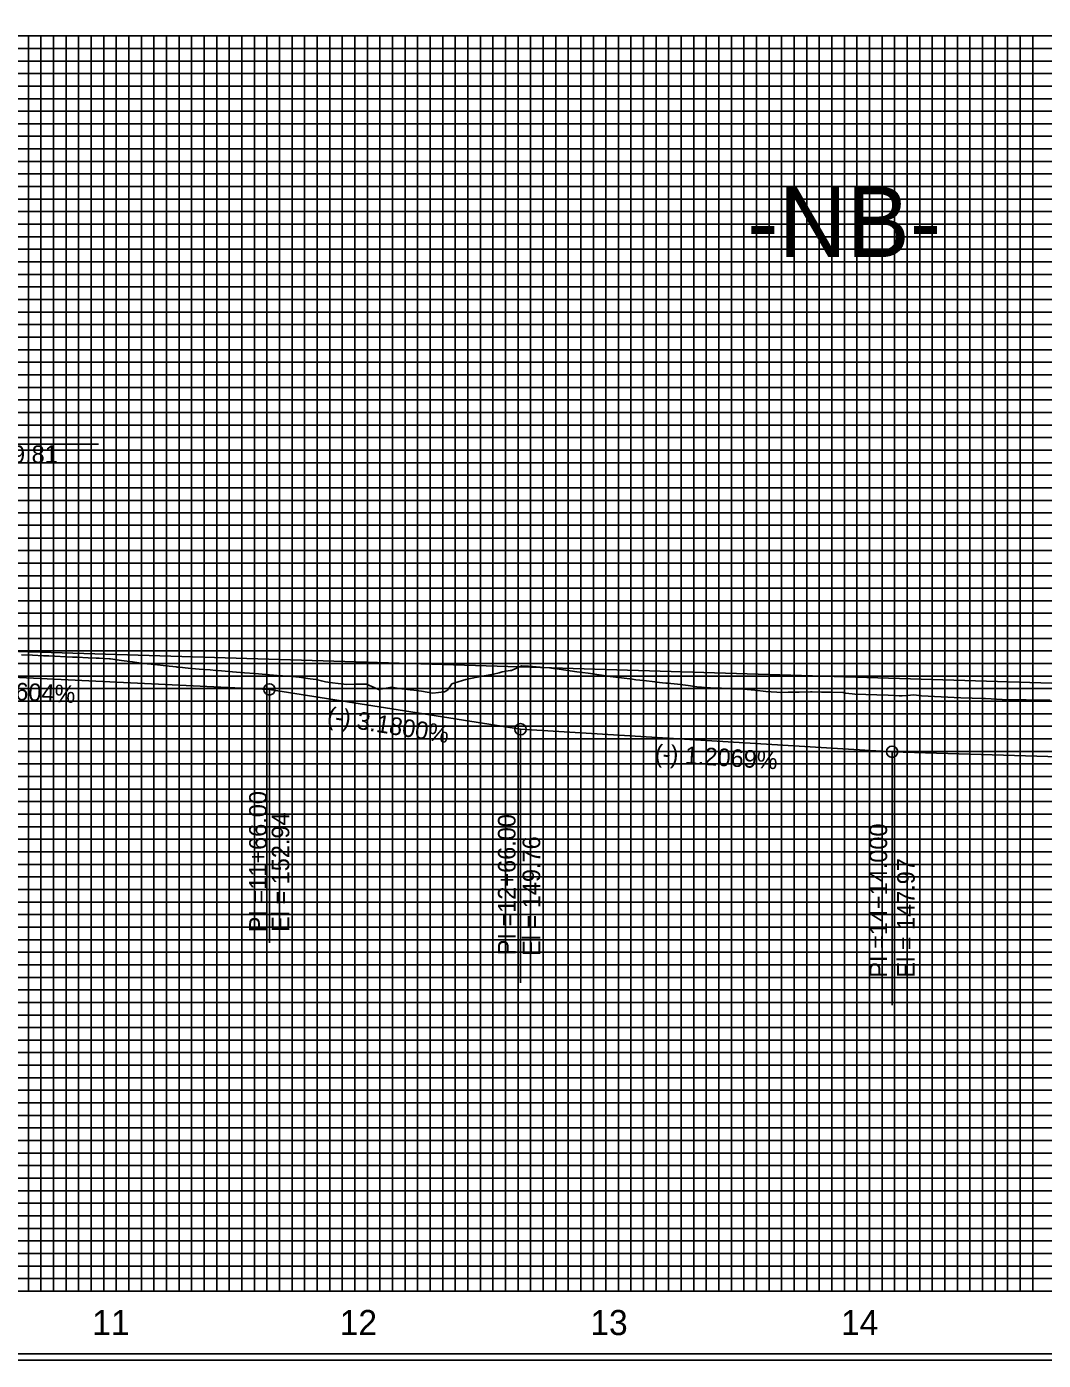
# Model space of a CAD drawing. Extents: x 573468 to 580768, y -57414 to -51768.
# Drawn here: x 579215 to 579619, y -55191 to -54660 of the extents above; entities that cross this region are included whole.
import ezdxf

# ---------------------------------------------------------------- set-up
doc = ezdxf.new("R2010")
doc.units = 0
for name, color, linetype in [('Exist Vertical Profile Ground Line', 7, 'Continuous'), ('Exist Vertical Profile Horizontal Axis Label Major', 7, 'Continuous'), ('Prop Grid Mask', 7, 'Continuous'), ('Prop PFL Text', 7, 'Continuous'), ('Prop Vertical Profile Ditch Grade Right', 7, 'Continuous'), ('Prop Vertical Profile Ditch Grade Right Label', 7, 'Continuous'), ('Prop Vertical Profile Grade', 7, 'Continuous'), ('Prop VPI Ditch Grade Right Label', 7, 'Continuous'), ('Sheet DOT Grid CELL', 7, 'Continuous'), ('Sheet Layout Profile Border Port 2', 7, 'Continuous'), ('Sheet Plot Border Inside CELL', 7, 'Continuous'), ('Sheet Profile CELL', 7, 'Continuous'), ('Sheet Profile Grid Major CELL', 7, 'Continuous'), ('Sheet Profile Grid Middle CELL', 7, 'Continuous'), ('Sheet Profile Grid Minor CELL', 7, 'Continuous')]:
    doc.layers.add(name, color=color, linetype=linetype)

msp = doc.modelspace()

# ---------------------------------------------------------------- linework, layer by layer
at = {"layer": 'Exist Vertical Profile Ground Line'}
for points in [[(579212.43, -54910.09), (579216.86, -54910.27), (579221.28, -54910.45), (579223.28, -54910.54), (579225.71, -54910.65), (579230.13, -54910.87), (579232.72, -54911), (579234.56, -54911.07), (579238.99, -54911.25), (579242.22, -54911.37), (579243.41, -54911.43), (579247.48, -54911.64), (579247.84, -54911.69), (579252.26, -54912.31), (579256.69, -54912.91), (579260.14, -54913.38), (579261.11, -54913.49), (579265.54, -54913.97), (579269.96, -54914.45), (579274.07, -54914.89), (579274.39, -54914.93), (579275.36, -54915.04), (579278.81, -54915.35), (579283.24, -54915.74), (579287.66, -54916.12), (579289.84, -54916.31), (579292.09, -54916.5), (579296.52, -54916.87), (579298.15, -54917.01), (579301.24, -54917.24), (579305.37, -54917.56), (579309.79, -54917.91), (579314.22, -54918.25), (579318.64, -54918.59), (579321.75, -54918.82), (579323.07, -54919.01), (579327.49, -54919.63), (579329.77, -54919.95), (579331.92, -54920.44), (579333.59, -54920.81), (579336.34, -54921.17), (579340.77, -54921.74), (579341.75, -54921.87), (579345.2, -54921.8), (579349.62, -54921.72), (579349.92, -54921.71), (579354.05, -54923.63), (579354.7, -54923.94), (579358.47, -54923.26), (579359.84, -54923.01), (579362.9, -54923.45), (579366.21, -54923.91), (579367.32, -54924), (579368.73, -54924.15), (579371.75, -54924.6), (579376.3, -54925.39), (579378.56, -54925.08), (579380.6, -54924.85), (579380.94, -54924.81), (579382.1, -54924.13), (579383.86, -54921.59), (579385.02, -54921.25), (579389.45, -54919.97), (579393.87, -54919.04), (579397.59, -54918.25), (579398.3, -54918.14), (579400.46, -54917.8), (579402.73, -54917.22), (579403.94, -54916.9), (579405.52, -54916.62), (579407.15, -54916.34), (579407.59, -54916.27), (579411.58, -54914.44), (579414.4, -54914.55), (579416, -54914.69), (579420.43, -54915.1), (579422.81, -54915.32), (579424.41, -54915.48), (579424.85, -54915.54), (579429.28, -54916.18), (579433.7, -54916.81), (579438.13, -54917.44), (579442.55, -54918.07), (579446.98, -54918.69), (579448.07, -54918.85), (579451.41, -54919.26), (579455.83, -54919.82), (579457.12, -54919.98), (579460.26, -54920.34), (579464.68, -54920.85), (579466.56, -54921.07), (579467.82, -54921.2), (579469.11, -54921.33), (579469.79, -54921.4), (579473.7, -54921.71), (579477.96, -54922.29), (579482.38, -54922.9), (579483.28, -54923.02), (579484.16, -54923.13), (579484.53, -54923.15), (579486.81, -54923.24)], [(579486.81, -54923.24), (579491.23, -54923.4), (579495.66, -54923.56), (579500.08, -54923.73), (579504.51, -54924.19), (579508.94, -54924.64), (579511.05, -54924.85), (579513.36, -54925), (579514.73, -54925.09), (579517.79, -54925.02), (579522.21, -54924.91), (579526.64, -54924.8), (579527.43, -54924.78), (579531.06, -54924.92), (579533.39, -54925.01), (579535.49, -54925.02), (579539.6, -54925.04), (579539.91, -54925.14), (579540.58, -54925.34), (579543.32, -54925.68), (579544.34, -54925.72), (579548.76, -54925.88), (579553.19, -54926.04), (579557.62, -54926.2), (579562.04, -54926.36), (579563.25, -54926.4), (579566.47, -54926.15), (579567.86, -54926.03), (579570.89, -54926.4), (579586.52, -54927.23), (579595.63, -54927.48), (579596.44, -54927.51), (579603.07, -54927.83), (579622.15, -54928.11)]]:
    msp.add_lwpolyline(points, dxfattribs=at)
at = {"layer": 'Prop Grid Mask'}
msp.add_lwpolyline([(579495.21, -54713.55), (579595.21, -54713.55), (579595.21, -54763.55), (579495.21, -54763.55)], close=True, dxfattribs=at)
at = {"layer": 'Prop PFL Text'}
msp.add_line((579145.02, -54826.15), (579243.08, -54826.15), dxfattribs=at)
at = {"layer": 'Prop Vertical Profile Ditch Grade Right'}
msp.add_lwpolyline([(579109.21, -54914.15), (579311.21, -54923.85), (579411.21, -54939.75), (579559.21, -54948.68), (579909.21, -54959.25), (580001.21, -54968.2)], dxfattribs=at)
at = {"layer": 'Prop Vertical Profile Ditch Grade Right Label'}
for p, q in [((579311.21, -54923.85), (579311.21, -55024.81)), ((579411.21, -54939.75), (579411.21, -55040.71)), ((579559.21, -54948.68), (579559.21, -55049.64))]:
    msp.add_line(p, q, dxfattribs=at)
for centre in [(579311.21, -54923.85), (579411.21, -54939.75), (579559.21, -54948.68)]:
    msp.add_circle(centre, 2.25, dxfattribs=at)
at = {"layer": 'Prop Vertical Profile Grade'}
msp.add_line((579145.02, -54906.75), (579945.21, -54931.16), dxfattribs=at)
at = {"layer": 'Sheet DOT Grid CELL'}
for p, q in [((578845.21, -54663.55), (580345.1, -54663.55)), ((579245.21, -54663.55), (579245.21, -55163.55)), ((579295.21, -54663.55), (579295.21, -55163.55)), ((579345.21, -54663.55), (579345.21, -55163.55)), ((579395.21, -54663.55), (579395.21, -55163.55)), ((579445.21, -54663.55), (579445.21, -55163.55)), ((579495.21, -54663.55), (579495.21, -55163.55)), ((579545.21, -54663.55), (579545.21, -55163.55)), ((579595.21, -54663.55), (579595.21, -55163.55)), ((578845.21, -54713.55), (580345.1, -54713.55)), ((578845.21, -54763.55), (580345.1, -54763.55)), ((578845.21, -54813.55), (580345.1, -54813.55)), ((578845.21, -54863.55), (580345.1, -54863.55)), ((578845.21, -54913.55), (580345.1, -54913.55)), ((578845.21, -54963.55), (580345.1, -54963.55)), ((578845.21, -55013.55), (580345.1, -55013.55)), ((578845.21, -55063.55), (580345.1, -55063.55)), ((578845.21, -55113.55), (580345.1, -55113.55))]:
    msp.add_line(p, q, dxfattribs=at)
at = {"layer": 'Sheet Layout Profile Border Port 2'}
msp.add_lwpolyline([(578895.21, -54663.55), (580295.21, -54663.55), (580295.21, -55163.55), (578895.21, -55163.55)], close=True, dxfattribs=at)
at = {"layer": 'Sheet Plot Border Inside CELL'}
msp.add_lwpolyline([(578691.21, -55191.1), (580357.71, -55191.1), (580357.71, -54136), (578691.21, -54136)], close=True, dxfattribs=at)
at = {"layer": 'Sheet Profile CELL'}
for p, q in [((578845.21, -54663.55), (580345.21, -54663.55)), ((580345.21, -55163.55), (578845.21, -55163.55)), ((578845.21, -55188.55), (580345.21, -55188.55))]:
    msp.add_line(p, q, dxfattribs=at)
msp.add_lwpolyline([(580345.21, -54138.55), (578845.21, -54138.55), (578845.21, -55188.55), (580345.21, -55188.55)], close=True, dxfattribs=at)
at = {"layer": 'Sheet Profile Grid Major CELL'}
for p, q in [((579345.21, -54663.55), (579395.21, -54663.55)), ((579445.21, -54663.55), (579495.21, -54663.55)), ((579545.21, -54663.55), (579595.21, -54663.55))]:
    msp.add_line(p, q, dxfattribs=at)
for points in [[(579195.21, -55163.55), (579245.21, -55163.55), (579245.21, -54663.55), (579295.21, -54663.55), (579295.21, -55163.55), (579345.21, -55163.55), (579345.21, -54663.55), (579395.21, -54663.55), (579395.21, -55163.55), (579445.21, -55163.55), (579445.21, -54663.55), (579495.21, -54663.55), (579495.21, -55163.55), (579545.21, -55163.55), (579545.21, -54663.55), (579595.21, -54663.55), (579595.21, -55163.55), (579645.21, -55163.55)], [(580345.21, -54713.55), (578845.21, -54713.55)], [(580345.21, -54763.55), (578845.21, -54763.55), (578845.21, -54813.55), (580345.21, -54813.55)], [(580345.21, -54863.55), (578845.21, -54863.55), (578845.21, -54913.55), (580345.21, -54913.55)], [(580345.21, -54963.55), (578845.21, -54963.55), (578845.21, -55013.55), (580345.21, -55013.55)], [(580345.21, -55063.55), (578845.21, -55063.55), (578845.21, -55063.55), (578845.21, -55113.55), (580345.21, -55113.55)], [(580345.21, -55163.55), (578845.21, -55163.55)]]:
    msp.add_lwpolyline(points, dxfattribs=at)
at = {"layer": 'Sheet Profile Grid Middle CELL'}
for points in [[(579170.21, -54663.55), (579220.21, -54663.55), (579220.21, -55163.55), (579270.21, -55163.55), (579270.21, -54663.55), (579320.21, -54663.55), (579320.21, -55163.55), (579370.21, -55163.55), (579370.21, -54663.55), (579420.21, -54663.55), (579420.21, -55163.55), (579470.21, -55163.55), (579470.21, -55163.55), (579470.21, -54663.55), (579520.21, -54663.55), (579520.21, -55163.55), (579570.21, -55163.55), (579570.21, -54663.55), (579620.21, -54663.55)], [(578845.21, -54688.55), (580345.21, -54688.55)], [(580345.21, -54738.55), (578845.21, -54738.55), (578845.21, -54788.55), (580345.21, -54788.55)], [(580345.21, -54838.55), (578845.21, -54838.55), (578845.21, -54888.55), (580345.21, -54888.55)], [(580345.21, -54938.55), (578845.21, -54938.55), (578845.21, -54988.55), (580345.21, -54988.55)], [(580345.21, -55038.55), (578845.21, -55038.55), (578845.21, -55088.55), (580345.21, -55088.55)], [(580345.21, -55138.55), (578845.21, -55138.55)]]:
    msp.add_lwpolyline(points, dxfattribs=at)
at = {"layer": 'Sheet Profile Grid Minor CELL'}
for p, q in [((578895.21, -54668.55), (580295.21, -54668.55)), ((580295.21, -54673.55), (578895.21, -54673.55)), ((578895.21, -54678.55), (580295.21, -54678.55)), ((580295.21, -54683.55), (578895.21, -54683.55)), ((578895.21, -54693.55), (580295.21, -54693.55)), ((580295.21, -54698.55), (578895.21, -54698.55)), ((578895.21, -54703.55), (580295.21, -54703.55)), ((580295.21, -54708.55), (578895.21, -54708.55)), ((578895.21, -54718.55), (580295.21, -54718.55)), ((580295.21, -54723.55), (578895.21, -54723.55)), ((578895.21, -54728.55), (580295.21, -54728.55)), ((580295.21, -54733.55), (578895.21, -54733.55)), ((578895.21, -54743.55), (580295.21, -54743.55)), ((580295.21, -54748.55), (578895.21, -54748.55)), ((578895.21, -54753.55), (580295.21, -54753.55)), ((580295.21, -54758.55), (578895.21, -54758.55)), ((578895.21, -54768.55), (580295.21, -54768.55)), ((580295.21, -54773.55), (578895.21, -54773.55)), ((578895.21, -54778.55), (580295.21, -54778.55)), ((580295.21, -54783.55), (578895.21, -54783.55)), ((578895.21, -54793.55), (580295.21, -54793.55)), ((580295.21, -54798.55), (578895.21, -54798.55)), ((578895.21, -54803.55), (580295.21, -54803.55)), ((580295.21, -54808.55), (578895.21, -54808.55)), ((578895.21, -54818.55), (580295.21, -54818.55)), ((580295.21, -54823.55), (578895.21, -54823.55)), ((578895.21, -54828.55), (580295.21, -54828.55)), ((580295.21, -54833.55), (578895.21, -54833.55)), ((578895.21, -54843.55), (580295.21, -54843.55)), ((580295.21, -54848.55), (578895.21, -54848.55)), ((578895.21, -54853.55), (580295.21, -54853.55)), ((580295.21, -54858.55), (578895.21, -54858.4)), ((578895.21, -54868.55), (580295.21, -54868.55)), ((580295.21, -54873.55), (578895.21, -54873.55)), ((578895.21, -54878.55), (580295.21, -54878.55)), ((580295.21, -54883.55), (578895.21, -54883.55)), ((578895.21, -54893.55), (580295.21, -54893.55)), ((580295.21, -54898.55), (578895.21, -54898.55)), ((578895.21, -54903.55), (580295.21, -54903.55)), ((580295.21, -54908.55), (578895.21, -54908.55)), ((578895.21, -54918.55), (580295.21, -54918.55)), ((580295.21, -54923.55), (578895.21, -54923.55)), ((578895.21, -54928.55), (580295.21, -54928.55)), ((580295.21, -54933.55), (578895.21, -54933.55)), ((578895.21, -54943.55), (580295.21, -54943.55)), ((580295.21, -54948.55), (578895.21, -54948.55)), ((578895.21, -54953.55), (580295.21, -54953.55)), ((580295.21, -54958.55), (578895.21, -54958.55)), ((578895.21, -54968.55), (580295.21, -54968.55)), ((580295.21, -54973.55), (578895.21, -54973.55)), ((578895.21, -54978.55), (580295.21, -54978.55)), ((580295.21, -54983.55), (578895.21, -54983.55)), ((578895.21, -54993.55), (580295.21, -54993.55)), ((580295.21, -54998.55), (578895.21, -54998.55)), ((578895.21, -55003.55), (580295.21, -55003.55)), ((580295.21, -55008.55), (578895.21, -55008.55)), ((578895.21, -55018.55), (580295.21, -55018.55)), ((580295.21, -55023.55), (578895.21, -55023.55)), ((578895.21, -55028.55), (580295.21, -55028.55)), ((580295.21, -55033.55), (578895.21, -55033.55)), ((578895.21, -55043.55), (580295.21, -55043.55)), ((580295.21, -55048.55), (578895.21, -55048.55)), ((578895.21, -55053.55), (580295.21, -55053.55)), ((580295.21, -55058.55), (578895.21, -55058.55)), ((578895.21, -55068.55), (580295.21, -55068.55)), ((580295.21, -55073.55), (578895.21, -55073.55)), ((578895.21, -55078.55), (580295.21, -55078.55)), ((580295.21, -55083.55), (578895.21, -55083.55)), ((578895.21, -55093.55), (580295.21, -55093.55)), ((580295.21, -55098.55), (578895.21, -55098.55)), ((578895.21, -55103.55), (580295.21, -55103.55)), ((580295.21, -55108.55), (578895.21, -55108.55)), ((578895.21, -55118.55), (580295.21, -55118.55)), ((580295.21, -55123.55), (578895.21, -55123.55)), ((578895.21, -55128.55), (580295.21, -55128.55)), ((580295.21, -55133.55), (578895.21, -55133.55)), ((578895.21, -55143.55), (580295.21, -55143.55)), ((580295.21, -55148.55), (578895.21, -55148.55)), ((578895.21, -55153.55), (580295.21, -55153.55)), ((578895.21, -55158.55), (580295.21, -55158.55))]:
    msp.add_line(p, q, dxfattribs=at)
for points in [[(579210.21, -55163.55), (579215.21, -55163.55), (579215.21, -54663.55), (579225.21, -54663.55), (579225.21, -55163.55), (579230.21, -55163.55), (579230.21, -54663.55), (579235.21, -54663.55), (579235.21, -55163.55), (579240.21, -55163.55), (579240.21, -54663.55), (579250.21, -54663.55), (579250.21, -55163.55), (579255.21, -55163.55), (579255.21, -54663.55), (579260.21, -54663.55), (579260.21, -55163.55), (579265.21, -55163.55), (579265.21, -54663.55), (579275.21, -54663.55), (579275.21, -55163.55), (579280.21, -55163.55), (579280.21, -54663.55), (579285.21, -54663.55), (579285.21, -55163.55), (579290.21, -55163.55), (579290.21, -54663.55), (579300.21, -54663.55), (579300.21, -55163.55), (579305.21, -55163.55), (579305.21, -54663.55), (579310.21, -54663.55), (579310.21, -55163.55), (579315.21, -55163.55), (579315.21, -54663.55), (579325.21, -54663.55), (579325.21, -55163.55), (579330.21, -55163.55), (579330.21, -54663.55), (579335.21, -54663.55), (579335.21, -55163.55), (579340.21, -55163.55), (579340.21, -54663.55), (579350.21, -54663.55), (579350.21, -55163.55), (579355.21, -55163.55), (579355.21, -54663.55), (579360.21, -54663.55), (579360.21, -55163.55), (579365.21, -55163.55), (579365.21, -54663.55), (579375.21, -54663.55), (579375.21, -55163.55), (579380.21, -55163.55), (579380.21, -54663.55), (579385.21, -54663.55), (579385.21, -55163.55), (579390.21, -55163.55), (579390.21, -54663.55), (579400.21, -54663.55), (579400.21, -55163.55), (579405.21, -55163.55), (579405.21, -54663.55), (579410.21, -54663.55), (579410.21, -55163.55), (579415.21, -55163.55), (579415.21, -54663.55), (579425.21, -54663.55)], [(579425.21, -54663.55), (579425.21, -55163.55), (579430.21, -55163.55), (579430.21, -54663.55), (579435.21, -54663.55), (579435.21, -55163.55), (579440.21, -55163.55), (579440.21, -54663.55), (579450.21, -54663.55), (579450.21, -55163.55), (579455.21, -55163.55), (579455.21, -54663.55), (579460.21, -54663.55), (579460.21, -55163.55), (579465.21, -55163.55), (579465.21, -54663.55), (579475.21, -54663.55), (579475.21, -55163.55), (579480.21, -55163.55), (579480.21, -54663.55), (579485.21, -54663.55), (579485.21, -55163.55), (579490.21, -55163.55), (579490.21, -54663.55), (579500.21, -54663.55), (579500.21, -55163.55), (579505.21, -55163.55), (579505.21, -54663.55), (579510.21, -54663.55), (579510.21, -55163.55), (579515.21, -55163.55), (579515.21, -54663.55), (579525.21, -54663.55), (579525.21, -55163.55), (579530.21, -55163.55), (579530.21, -54663.55), (579535.21, -54663.55), (579535.21, -55163.55), (579540.21, -55163.55), (579540.21, -54663.55), (579550.21, -54663.55), (579550.21, -55163.55), (579550.21, -55163.55), (579555.21, -55163.55), (579555.21, -54663.55), (579560.21, -54663.55), (579560.21, -55163.55), (579565.21, -55163.55), (579565.21, -54663.55), (579575.21, -54663.55), (579575.21, -55163.55), (579580.21, -55163.55), (579580.21, -54663.55), (579585.21, -54663.55), (579585.21, -55163.55), (579590.21, -55163.55), (579590.21, -54663.55), (579600.21, -54663.55), (579600.21, -55163.55), (579605.21, -55163.55), (579605.21, -54663.55), (579610.21, -54663.55), (579610.21, -55163.55), (579615.21, -55163.55), (579615.21, -54663.55), (579625.21, -54663.55)]]:
    msp.add_lwpolyline(points, dxfattribs=at)

# ---------------------------------------------------------------- texts
at = {"layer": 'Exist Vertical Profile Horizontal Axis Label Major'}
for s, p in [('11', (579240.64, -55181.05)), ('12', (579339.19, -55181.05)), ('13', (579439.02, -55181.05)), ('14', (579538.86, -55181.05))]:
    msp.add_text(s, height=10, dxfattribs=at).set_placement(p)
at = {"layer": 'Prop PFL Text'}
for s, height, p in [('-NB-', 28.125, (579501.43, -54751.68)), ('-NB- STA. 9+99.81', 7, (579147.55, -54833.69))]:
    msp.add_text(s, height=height, dxfattribs=at).set_placement(p)
at = {"layer": 'Prop Vertical Profile Ditch Grade Right Label'}
for s, rotation, p in [('(-) 0.9604%', 357.2508, (579184.91, -54926.94)), ('(-) 3.1800%', 350.9656, (579333.86, -54937.64)), ('(-) 1.2069%', 356.5467, (579464.57, -54952.75))]:
    msp.add_text(s, height=7, rotation=rotation, dxfattribs=at).set_placement(p)
at = {"layer": 'Prop VPI Ditch Grade Right Label'}
for s, p in [('PI =11+66.00', (579310.13, -55020.57)), ('El = 152.94', (579319.11, -55020.48)), ('PI =12+66.00', (579409.21, -55029.75)), ('PI =14+14.000', (579557.21, -55038.68)), ('El = 149.76', (579419.04, -55030)), ('El = 147.97', (579568.21, -55038.68))]:
    msp.add_text(s, height=7, rotation=90, dxfattribs=at).set_placement(p)

doc.saveas('drawing.dxf')
